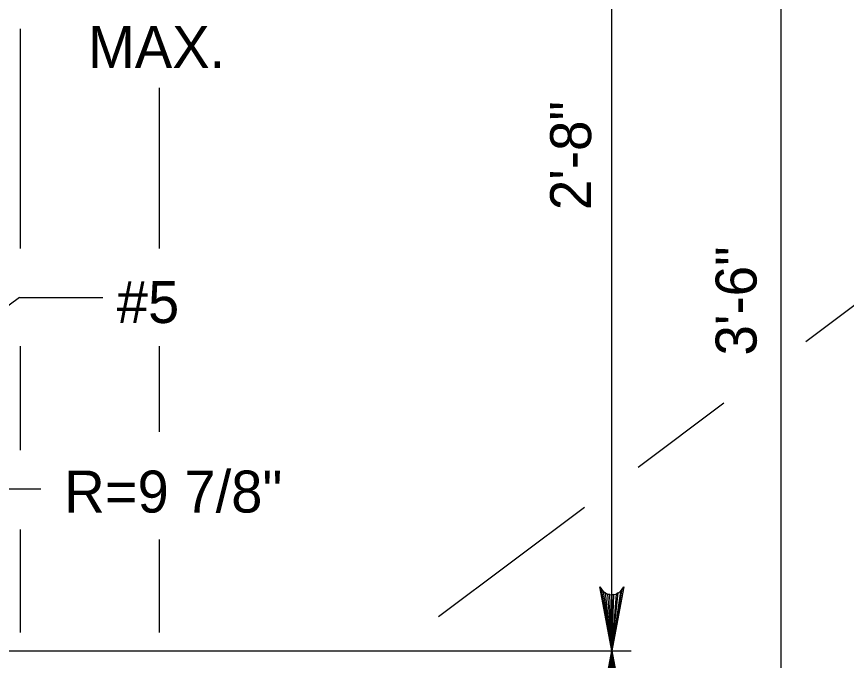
# Model space of a CAD drawing. Extents: x 638167 to 640248, y 296544 to 298920.
# Drawn here: x 638334.5 to 638395.2, y 296717.4 to 296764.5 of the extents above; entities that cross this region are included whole.
import ezdxf

# ---------------------------------------------------------------- set-up
doc = ezdxf.new("R2010")
doc.units = 0
doc.layers.add('1', color=7, linetype='Continuous')

msp = doc.modelspace()

# ---------------------------------------------------------------- linework, layer by layer
at = {"layer": '1'}
for p, q in [((638378.054, 296668.16), (638378.054, 296799.339)), ((638390.449, 296692.659), (638390.449, 296799.339)), ((638334.788, 296747.498), (638334.788, 296763.587)), ((638344.948, 296747.498), (638344.948, 296759.263)), ((638392.24, 296740.7), (638396.962, 296744.239)), ((638334.703, 296743.926), (638302.706, 296720.223)), ((638334.703, 296743.926), (638340.801, 296743.926)), ((638334.788, 296732.751), (638334.788, 296740.348)), ((638344.948, 296734.091), (638344.948, 296740.348)), ((638379.988, 296731.515), (638386.243, 296736.204)), ((638331.378, 296729.927), (638336.267, 296729.927)), ((638365.38, 296720.566), (638376.054, 296728.567)), ((638334.788, 296719.409), (638334.788, 296726.941)), ((638344.948, 296719.409), (638344.948, 296726.219)), ((638325.13, 296718.059), (638379.456, 296718.059))]:
    msp.add_line(p, q, dxfattribs=at)
for points in [[(638378.054, 296718.059), (638377.173, 296722.757), (638377.299, 296722.576), (638377.424, 296722.395), (638377.582, 296722.301), (638377.739, 296722.208), (638377.897, 296722.181), (638378.054, 296722.154), (638378.212, 296722.181), (638378.369, 296722.208), (638378.527, 296722.301), (638378.684, 296722.395), (638378.81, 296722.576), (638378.935, 296722.757), (638378.054, 296718.059), (638378.81, 296722.576), (638378.684, 296722.395), (638378.054, 296718.059), (638378.527, 296722.301), (638378.369, 296722.208), (638378.054, 296718.059), (638378.212, 296722.181), (638378.054, 296722.154), (638378.054, 296718.059), (638377.897, 296722.181), (638377.739, 296722.208), (638378.054, 296718.059), (638377.582, 296722.301), (638377.424, 296722.395), (638378.054, 296718.059), (638377.299, 296722.576)], [(638377.173, 296713.362), (638378.054, 296718.059), (638377.299, 296713.543)], [(638377.424, 296713.723), (638378.054, 296718.059), (638377.582, 296713.817)], [(638377.739, 296713.91), (638378.054, 296718.059), (638377.897, 296713.937)], [(638378.054, 296718.059), (638378.935, 296713.362)], [(638378.054, 296713.964), (638378.054, 296718.059), (638378.212, 296713.937)], [(638378.369, 296713.91), (638378.054, 296718.059), (638378.527, 296713.817)], [(638378.684, 296713.723), (638378.054, 296718.059), (638378.81, 296713.543)]]:
    msp.add_lwpolyline(points, dxfattribs=at)

# ---------------------------------------------------------------- texts
for s, p in [('MAX.', (638339.727, 296760.718)), ('#5', (638341.835, 296742.053)), ('R=9 7/8"', (638337.986, 296728.181))]:
    msp.add_text(s, height=3.072, dxfattribs=at).set_placement(p)
for s, p in [('2\'-8"', (638376.538, 296750.311)), ('3\'-6"', (638388.646, 296739.674))]:
    msp.add_text(s, height=3, rotation=90, dxfattribs=at).set_placement(p)

doc.saveas('drawing.dxf')
